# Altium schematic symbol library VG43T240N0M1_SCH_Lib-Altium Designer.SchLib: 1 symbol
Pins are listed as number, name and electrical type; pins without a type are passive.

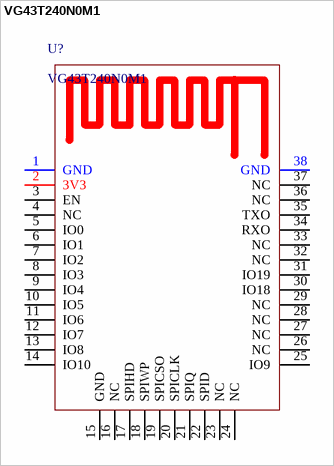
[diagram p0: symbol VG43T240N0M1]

## VG43T240N0M1
designator U?
pins: 1 GND, 2 3V3, 3 EN, 4 NC, 5 IO0, 6 IO1, 7 IO2, 8 IO3, 9 IO4, 10 IO5, 11 IO6, 12 IO7, 13 IO8, 14 IO10, 15 GND, 16 NC, 17 SPIHD, 18 SPIWP, 19 SPICSO, 20 SPICLK, 21 SPIQ, 22 SPID, 23 NC, 24 NC, 25 IO9, 26 NC, 27 NC, 28 NC, 29 NC, 30 IO18, 31 IO19, 32 NC, 33 NC, 34 RXO, 35 TXO, 36 NC, 37 NC, 38 GND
